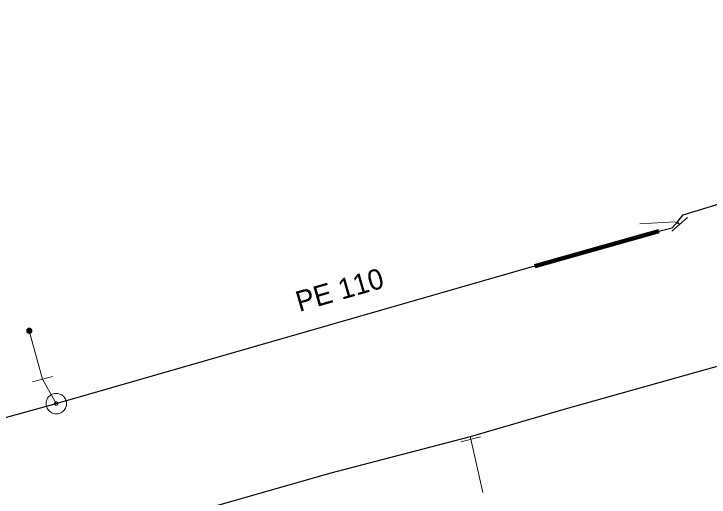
# Model space of a CAD drawing. Extents: x -690254 to -689100, y -975264 to -974703.
# Drawn here: x -689647.08 to -689613.11, y -975037.67 to -975014.07 of the extents above; entities that cross this region are included whole.
import ezdxf

# ---------------------------------------------------------------- set-up
doc = ezdxf.new("R2010")
doc.units = 0
doc.header["$LTSCALE"] = 0.4
for name, color, linetype, lineweight in [('1', 7, 'Continuous', 13), ('13', 7, 'Continuous', 13), ('14', 7, 'Continuous', 13), ('17', 7, 'Continuous', 25), ('3', 7, 'Continuous', 106), ('34', 7, 'Continuous', 13), ('47', 7, 'Continuous', 13), ('9', 7, 'Continuous', 13)]:
    doc.layers.add(name, color=color, linetype=linetype, lineweight=lineweight)

msp = doc.modelspace()

# ---------------------------------------------------------------- linework, layer by layer
at = {"layer": '13'}
msp.add_line((-689624.759, -975034.852), (-689624.16, -975037.445), dxfattribs=at)
msp.add_lwpolyline([(-689614.546, -975024.351), (-689614.776, -975024.232), (-689616.489, -975024.316)], dxfattribs=at)
at = {"layer": '14'}
for p, q in [((-689614.659, -975024.223), (-689614.546, -975024.351)), ((-689624.787, -975034.736), (-689624.759, -975034.852))]:
    msp.add_line(p, q, dxfattribs=at)
msp.add_lwpolyline([(-689645.011, -975033.107), (-689645.684, -975031.908), (-689646.329, -975029.548)], dxfattribs=at)
at = {"layer": '17'}
for points in [[(-689645.011, -975033.107), (-689621.745, -975026.405), (-689621.62, -975026.388), (-689615.567, -975024.675), (-689614.917, -975024.517), (-689614.659, -975024.223), (-689614.375, -975023.884), (-689611.447, -975022.993), (-689600.274, -975019.828), (-689599.903, -975019.734), (-689592.52, -975017.662), (-689580.94, -975014.068)], [(-689585.619, -975023.64), (-689592.723, -975025.675), (-689611.551, -975030.974), (-689620.085, -975033.361), (-689624.787, -975034.736), (-689631.651, -975036.524), (-689643.153, -975039.808), (-689643.343, -975039.867)], [(-689652.269, -975035.174), (-689651.761, -975035.033), (-689648.094, -975033.951), (-689645.011, -975033.107)]]:
    msp.add_lwpolyline(points, dxfattribs=at)
at = {"layer": '3'}
msp.add_line((-689621.62, -975026.388), (-689615.567, -975024.675), dxfattribs=at)
at = {"layer": '3', "lineweight": 100}
msp.add_line((-689621.62, -975026.388), (-689615.567, -975024.675), dxfattribs=at)
at = {"layer": '34'}
for p, q in [((-689614.171, -975024.019), (-689614.921, -975024.681)), ((-689646.166, -975032.04), (-689645.201, -975031.776)), ((-689624.274, -975034.73), (-689625.244, -975034.972))]:
    msp.add_line(p, q, dxfattribs=at)
at = {"layer": '47'}
for points in [[(-689644.528, -975032.975), (-689644.545, -975032.925), (-689644.566, -975032.877), (-689644.593, -975032.833), (-689644.623, -975032.79), (-689644.659, -975032.751), (-689644.698, -975032.716), (-689644.741, -975032.686), (-689644.786, -975032.661), (-689644.834, -975032.639), (-689644.884, -975032.623), (-689644.935, -975032.612), (-689644.987, -975032.608), (-689645.039, -975032.607), (-689645.091, -975032.613), (-689645.142, -975032.624), (-689645.192, -975032.641), (-689645.24, -975032.662), (-689645.285, -975032.689), (-689645.327, -975032.719), (-689645.366, -975032.755), (-689645.401, -975032.794), (-689645.432, -975032.837), (-689645.457, -975032.882), (-689645.479, -975032.93), (-689645.494, -975032.98), (-689645.505, -975033.031), (-689645.51, -975033.084), (-689645.51, -975033.135), (-689645.504, -975033.187), (-689645.493, -975033.238), (-689645.476, -975033.288), (-689645.455, -975033.336), (-689645.429, -975033.382), (-689645.398, -975033.423), (-689645.362, -975033.462), (-689645.324, -975033.497), (-689645.281, -975033.528), (-689645.235, -975033.554), (-689645.187, -975033.575), (-689645.137, -975033.59), (-689645.086, -975033.601), (-689645.034, -975033.607), (-689644.982, -975033.606), (-689644.93, -975033.6), (-689644.879, -975033.589), (-689644.829, -975033.572), (-689644.781, -975033.551), (-689644.736, -975033.525), (-689644.694, -975033.494), (-689644.655, -975033.458), (-689644.62, -975033.42), (-689644.59, -975033.377), (-689644.564, -975033.332), (-689644.543, -975033.283), (-689644.527, -975033.233), (-689644.516, -975033.182), (-689644.511, -975033.131), (-689644.511, -975033.078), (-689644.517, -975033.026)], [(-689644.931, -975033.085), (-689644.934, -975033.076), (-689644.938, -975033.069), (-689644.942, -975033.062), (-689644.947, -975033.055), (-689644.953, -975033.048), (-689644.96, -975033.043), (-689644.966, -975033.037), (-689644.974, -975033.033), (-689644.982, -975033.03), (-689644.99, -975033.027), (-689644.998, -975033.025), (-689645.007, -975033.025), (-689645.015, -975033.025), (-689645.023, -975033.025), (-689645.032, -975033.027), (-689645.041, -975033.03), (-689645.048, -975033.034), (-689645.055, -975033.038), (-689645.062, -975033.043), (-689645.069, -975033.049), (-689645.074, -975033.056), (-689645.08, -975033.062), (-689645.084, -975033.07), (-689645.088, -975033.078), (-689645.09, -975033.086), (-689645.092, -975033.094), (-689645.092, -975033.103), (-689645.092, -975033.111), (-689645.092, -975033.119), (-689645.09, -975033.128), (-689645.087, -975033.137), (-689645.083, -975033.144), (-689645.079, -975033.151), (-689645.074, -975033.158), (-689645.068, -975033.165), (-689645.062, -975033.17), (-689645.055, -975033.176), (-689645.047, -975033.18), (-689645.039, -975033.184), (-689645.031, -975033.186), (-689645.023, -975033.188), (-689645.014, -975033.188), (-689645.006, -975033.188), (-689644.998, -975033.188), (-689644.989, -975033.186), (-689644.98, -975033.183), (-689644.973, -975033.179), (-689644.966, -975033.175), (-689644.959, -975033.17), (-689644.952, -975033.164), (-689644.947, -975033.158), (-689644.941, -975033.151), (-689644.937, -975033.143), (-689644.934, -975033.135), (-689644.931, -975033.127), (-689644.929, -975033.119), (-689644.929, -975033.11), (-689644.929, -975033.102), (-689644.929, -975033.094)]]:
    msp.add_lwpolyline(points, close=True, dxfattribs=at)
at = {"layer": '9'}
for points in [[(-689646.455, -975029.548), (-689646.455, -975029.561), (-689646.453, -975029.574), (-689646.45, -975029.587), (-689646.445, -975029.599), (-689646.439, -975029.611), (-689646.432, -975029.622), (-689646.424, -975029.632), (-689646.414, -975029.642), (-689646.404, -975029.65), (-689646.393, -975029.657), (-689646.381, -975029.663), (-689646.369, -975029.668), (-689646.356, -975029.671), (-689646.343, -975029.673), (-689646.33, -975029.675), (-689646.317, -975029.674), (-689646.304, -975029.672), (-689646.291, -975029.669), (-689646.279, -975029.664), (-689646.267, -975029.658), (-689646.256, -975029.651), (-689646.246, -975029.643), (-689646.236, -975029.633), (-689646.228, -975029.623), (-689646.221, -975029.612), (-689646.215, -975029.6), (-689646.21, -975029.588), (-689646.207, -975029.575), (-689646.205, -975029.562), (-689646.203, -975029.549), (-689646.204, -975029.536), (-689646.206, -975029.523), (-689646.209, -975029.51), (-689646.214, -975029.498), (-689646.22, -975029.486), (-689646.227, -975029.475), (-689646.235, -975029.465), (-689646.245, -975029.455), (-689646.255, -975029.447), (-689646.266, -975029.44), (-689646.278, -975029.434), (-689646.29, -975029.429), (-689646.303, -975029.426), (-689646.316, -975029.424), (-689646.329, -975029.423), (-689646.342, -975029.423), (-689646.355, -975029.425), (-689646.368, -975029.428), (-689646.38, -975029.433), (-689646.392, -975029.439), (-689646.403, -975029.446), (-689646.413, -975029.454), (-689646.423, -975029.464), (-689646.431, -975029.474), (-689646.438, -975029.485), (-689646.444, -975029.497), (-689646.449, -975029.509), (-689646.452, -975029.522), (-689646.454, -975029.535)], [(-689646.435, -975029.548), (-689646.436, -975029.559), (-689646.434, -975029.57), (-689646.431, -975029.581), (-689646.427, -975029.591), (-689646.422, -975029.601), (-689646.416, -975029.61), (-689646.409, -975029.619), (-689646.401, -975029.627), (-689646.392, -975029.634), (-689646.383, -975029.64), (-689646.373, -975029.645), (-689646.363, -975029.649), (-689646.352, -975029.652), (-689646.341, -975029.655), (-689646.33, -975029.655), (-689646.319, -975029.655), (-689646.308, -975029.653), (-689646.297, -975029.65), (-689646.287, -975029.646), (-689646.277, -975029.641), (-689646.268, -975029.635), (-689646.259, -975029.628), (-689646.251, -975029.62), (-689646.244, -975029.611), (-689646.238, -975029.602), (-689646.233, -975029.592), (-689646.229, -975029.582), (-689646.226, -975029.571), (-689646.224, -975029.56), (-689646.223, -975029.549), (-689646.223, -975029.538), (-689646.225, -975029.527), (-689646.228, -975029.516), (-689646.232, -975029.506), (-689646.237, -975029.496), (-689646.243, -975029.487), (-689646.25, -975029.478), (-689646.258, -975029.47), (-689646.267, -975029.463), (-689646.276, -975029.457), (-689646.286, -975029.452), (-689646.296, -975029.448), (-689646.307, -975029.445), (-689646.318, -975029.443), (-689646.329, -975029.443), (-689646.34, -975029.442), (-689646.351, -975029.444), (-689646.362, -975029.447), (-689646.372, -975029.451), (-689646.382, -975029.456), (-689646.391, -975029.462), (-689646.4, -975029.469), (-689646.408, -975029.477), (-689646.415, -975029.486), (-689646.421, -975029.495), (-689646.426, -975029.505), (-689646.43, -975029.515), (-689646.433, -975029.526), (-689646.435, -975029.537)], [(-689646.416, -975029.548), (-689646.416, -975029.557), (-689646.415, -975029.566), (-689646.412, -975029.575), (-689646.409, -975029.583), (-689646.405, -975029.591), (-689646.4, -975029.599), (-689646.394, -975029.606), (-689646.388, -975029.612), (-689646.381, -975029.618), (-689646.373, -975029.623), (-689646.365, -975029.627), (-689646.357, -975029.63), (-689646.348, -975029.633), (-689646.339, -975029.634), (-689646.33, -975029.636), (-689646.321, -975029.635), (-689646.312, -975029.634), (-689646.303, -975029.631), (-689646.295, -975029.628), (-689646.287, -975029.624), (-689646.279, -975029.619), (-689646.272, -975029.613), (-689646.266, -975029.607), (-689646.26, -975029.6), (-689646.255, -975029.592), (-689646.251, -975029.584), (-689646.248, -975029.576), (-689646.245, -975029.567), (-689646.244, -975029.558), (-689646.242, -975029.549), (-689646.243, -975029.54), (-689646.244, -975029.531), (-689646.247, -975029.522), (-689646.25, -975029.514), (-689646.254, -975029.506), (-689646.259, -975029.498), (-689646.265, -975029.491), (-689646.271, -975029.485), (-689646.278, -975029.479), (-689646.286, -975029.474), (-689646.294, -975029.47), (-689646.302, -975029.467), (-689646.311, -975029.464), (-689646.32, -975029.463), (-689646.329, -975029.462), (-689646.338, -975029.462), (-689646.347, -975029.463), (-689646.356, -975029.466), (-689646.364, -975029.469), (-689646.372, -975029.473), (-689646.38, -975029.478), (-689646.387, -975029.484), (-689646.393, -975029.49), (-689646.399, -975029.497), (-689646.404, -975029.505), (-689646.408, -975029.513), (-689646.411, -975029.521), (-689646.414, -975029.53), (-689646.415, -975029.539)], [(-689646.396, -975029.548), (-689646.396, -975029.555), (-689646.395, -975029.562), (-689646.394, -975029.569), (-689646.391, -975029.575), (-689646.388, -975029.581), (-689646.384, -975029.587), (-689646.38, -975029.593), (-689646.375, -975029.598), (-689646.369, -975029.602), (-689646.363, -975029.606), (-689646.357, -975029.609), (-689646.351, -975029.612), (-689646.344, -975029.613), (-689646.337, -975029.616), (-689646.33, -975029.616), (-689646.323, -975029.616), (-689646.316, -975029.614), (-689646.309, -975029.613), (-689646.303, -975029.61), (-689646.296, -975029.607), (-689646.291, -975029.603), (-689646.285, -975029.599), (-689646.28, -975029.594), (-689646.276, -975029.588), (-689646.272, -975029.582), (-689646.269, -975029.576), (-689646.266, -975029.57), (-689646.264, -975029.563), (-689646.263, -975029.556), (-689646.262, -975029.549), (-689646.262, -975029.542), (-689646.263, -975029.535), (-689646.265, -975029.528), (-689646.268, -975029.522), (-689646.271, -975029.515), (-689646.275, -975029.51), (-689646.279, -975029.504), (-689646.284, -975029.499), (-689646.29, -975029.495), (-689646.295, -975029.491), (-689646.302, -975029.488), (-689646.308, -975029.485), (-689646.315, -975029.483), (-689646.322, -975029.482), (-689646.329, -975029.482), (-689646.336, -975029.482), (-689646.343, -975029.482), (-689646.35, -975029.484), (-689646.356, -975029.487), (-689646.362, -975029.49), (-689646.368, -975029.494), (-689646.374, -975029.498), (-689646.379, -975029.503), (-689646.383, -975029.509), (-689646.387, -975029.514), (-689646.39, -975029.521), (-689646.393, -975029.527), (-689646.394, -975029.534), (-689646.396, -975029.541)], [(-689646.376, -975029.548), (-689646.376, -975029.553), (-689646.376, -975029.558), (-689646.375, -975029.563), (-689646.373, -975029.567), (-689646.371, -975029.572), (-689646.368, -975029.576), (-689646.365, -975029.579), (-689646.361, -975029.583), (-689646.358, -975029.586), (-689646.354, -975029.589), (-689646.349, -975029.591), (-689646.345, -975029.593), (-689646.34, -975029.594), (-689646.335, -975029.596), (-689646.33, -975029.596), (-689646.325, -975029.596), (-689646.32, -975029.595), (-689646.315, -975029.594), (-689646.311, -975029.592), (-689646.306, -975029.59), (-689646.302, -975029.587), (-689646.298, -975029.584), (-689646.295, -975029.58), (-689646.292, -975029.577), (-689646.289, -975029.573), (-689646.287, -975029.568), (-689646.285, -975029.564), (-689646.284, -975029.559), (-689646.283, -975029.554), (-689646.282, -975029.549), (-689646.282, -975029.544), (-689646.283, -975029.539), (-689646.284, -975029.534), (-689646.286, -975029.53), (-689646.288, -975029.525), (-689646.291, -975029.521), (-689646.294, -975029.517), (-689646.297, -975029.514), (-689646.301, -975029.511), (-689646.305, -975029.508), (-689646.31, -975029.506), (-689646.314, -975029.504), (-689646.319, -975029.503), (-689646.324, -975029.502), (-689646.329, -975029.502), (-689646.334, -975029.502), (-689646.339, -975029.503), (-689646.344, -975029.503), (-689646.348, -975029.505), (-689646.353, -975029.507), (-689646.357, -975029.51), (-689646.36, -975029.513), (-689646.364, -975029.516), (-689646.367, -975029.52), (-689646.37, -975029.524), (-689646.372, -975029.529), (-689646.374, -975029.533), (-689646.375, -975029.538), (-689646.376, -975029.543)], [(-689646.356, -975029.548), (-689646.356, -975029.551), (-689646.357, -975029.554), (-689646.356, -975029.556), (-689646.355, -975029.559), (-689646.354, -975029.562), (-689646.352, -975029.564), (-689646.35, -975029.566), (-689646.348, -975029.568), (-689646.346, -975029.57), (-689646.344, -975029.572), (-689646.341, -975029.574), (-689646.338, -975029.575), (-689646.336, -975029.575), (-689646.333, -975029.576), (-689646.33, -975029.576), (-689646.327, -975029.576), (-689646.324, -975029.576), (-689646.321, -975029.575), (-689646.319, -975029.574), (-689646.316, -975029.573), (-689646.314, -975029.571), (-689646.311, -975029.569), (-689646.309, -975029.567), (-689646.308, -975029.565), (-689646.306, -975029.563), (-689646.305, -975029.56), (-689646.303, -975029.557), (-689646.303, -975029.555), (-689646.302, -975029.552), (-689646.301, -975029.549), (-689646.302, -975029.546), (-689646.302, -975029.543), (-689646.303, -975029.54), (-689646.304, -975029.538), (-689646.305, -975029.535), (-689646.307, -975029.533), (-689646.308, -975029.53), (-689646.31, -975029.528), (-689646.313, -975029.527), (-689646.315, -975029.525), (-689646.318, -975029.524), (-689646.32, -975029.523), (-689646.323, -975029.522), (-689646.326, -975029.522), (-689646.329, -975029.521), (-689646.332, -975029.522), (-689646.335, -975029.521), (-689646.337, -975029.523), (-689646.34, -975029.523), (-689646.343, -975029.524), (-689646.345, -975029.526), (-689646.347, -975029.527), (-689646.349, -975029.529), (-689646.351, -975029.532), (-689646.353, -975029.534), (-689646.354, -975029.537), (-689646.355, -975029.539), (-689646.356, -975029.542), (-689646.356, -975029.545)], [(-689646.337, -975029.548), (-689646.337, -975029.55), (-689646.337, -975029.55), (-689646.336, -975029.55), (-689646.336, -975029.552), (-689646.337, -975029.553), (-689646.335, -975029.553), (-689646.335, -975029.553), (-689646.335, -975029.555), (-689646.335, -975029.555), (-689646.334, -975029.556), (-689646.332, -975029.556), (-689646.332, -975029.556), (-689646.332, -975029.557), (-689646.33, -975029.557), (-689646.33, -975029.557), (-689646.329, -975029.557), (-689646.328, -975029.557), (-689646.328, -975029.556), (-689646.327, -975029.556), (-689646.325, -975029.556), (-689646.325, -975029.555), (-689646.325, -975029.555), (-689646.324, -975029.554), (-689646.324, -975029.554), (-689646.322, -975029.553), (-689646.322, -975029.552), (-689646.321, -975029.551), (-689646.321, -975029.551), (-689646.321, -975029.55), (-689646.321, -975029.549), (-689646.321, -975029.548), (-689646.321, -975029.547), (-689646.321, -975029.547), (-689646.322, -975029.546), (-689646.322, -975029.545), (-689646.323, -975029.544), (-689646.323, -975029.544), (-689646.324, -975029.543), (-689646.324, -975029.543), (-689646.325, -975029.542), (-689646.326, -975029.542), (-689646.327, -975029.541), (-689646.327, -975029.541), (-689646.328, -975029.541), (-689646.329, -975029.541), (-689646.33, -975029.541), (-689646.331, -975029.541), (-689646.331, -975029.541), (-689646.332, -975029.542), (-689646.333, -975029.541), (-689646.334, -975029.543), (-689646.334, -975029.543), (-689646.335, -975029.543), (-689646.335, -975029.543), (-689646.336, -975029.545), (-689646.336, -975029.546), (-689646.336, -975029.547), (-689646.337, -975029.547), (-689646.337, -975029.548)]]:
    msp.add_lwpolyline(points, close=True, dxfattribs=at)

# ---------------------------------------------------------------- texts
at = {"layer": '1'}
msp.add_text('PE 110', height=1, rotation=16, dxfattribs=at).set_placement((-689633.135, -975028.631))

doc.saveas('drawing.dxf')
